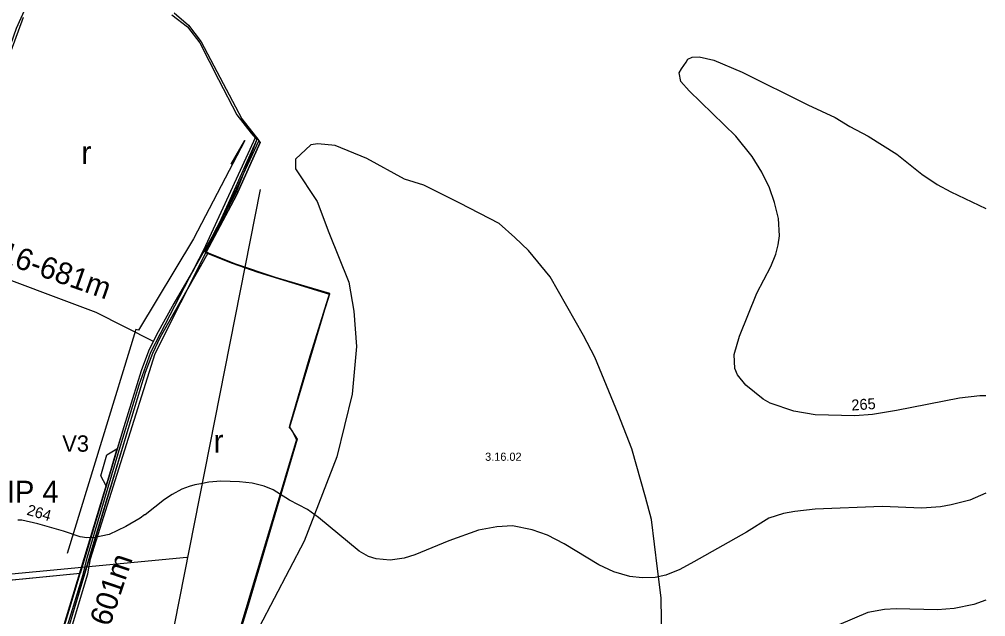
# Model space of a CAD drawing. Extents: x -662500 to -655523, y -1056000 to -1049993.
# Drawn here: x -659686 to -658798, y -1051897 to -1051349 of the extents above; entities that cross this region are included whole.
import ezdxf

# ---------------------------------------------------------------- set-up
doc = ezdxf.new("R2010")
doc.units = 0
for name, color, linetype in [('58', 7, 'Continuous'), ('Vrstva 1', 7, 'Continuous'), ('Vrstva 10', 7, 'Continuous'), ('Vrstva 15', 7, 'Continuous'), ('Vrstva 16', 7, 'Continuous'), ('Vrstva 18', 7, 'Continuous'), ('Vrstva 24', 7, 'Continuous'), ('Vrstva 44', 7, 'Continuous'), ('Vrstva 5', 7, 'Continuous'), ('Vrstva 52', 7, 'Continuous'), ('Vrstva 61', 7, 'Continuous'), ('Vrstva 7', 7, 'Continuous')]:
    doc.layers.add(name, color=color, linetype=linetype)

msp = doc.modelspace()

# ---------------------------------------------------------------- linework, layer by layer
at = {"layer": '58'}
for points in [[(-659819.9, -1051325.04), (-659837.72, -1051368.71), (-659869.54, -1051455.64), (-659887.19, -1051507.97), (-659838.36, -1051532.32), (-659759.05, -1051561.67), (-659712.51, -1051424.5), (-659688.44, -1051356.77), (-659655.81, -1051283.68)], [(-659545.76, -1051344.32), (-659531.38, -1051355.46), (-659520.03, -1051370.23), (-659502.95, -1051403.94), (-659485.94, -1051436.16), (-659472.84, -1051453.09), (-659468.98, -1051457.69), (-659467.67, -1051458.98), (-659486.82, -1051508.01), (-659515.44, -1051562.58), (-659514.06, -1051563.18), (-659490.41, -1051572.48), (-659466.8, -1051580.89), (-659400.85, -1051601.17), (-659419.91, -1051661.07), (-659437.32, -1051721.06), (-659438.03, -1051723.54), (-659435.89, -1051725.64), (-659431.04, -1051734.49), (-659517.29, -1052025.4)]]:
    msp.add_lwpolyline(points, dxfattribs=at)
at = {"layer": 'Vrstva 1'}
for points in [[(-659822.86, -1051335.88), (-659842.66, -1051387.23), (-659885.47, -1051507.41), (-659840.84, -1051529.9), (-659757.26, -1051561.49), (-659712.92, -1051430.24), (-659682.02, -1051346.44)], [(-659543.44, -1051342.71), (-659530.33, -1051353.77), (-659518.69, -1051369.3), (-659481.35, -1051440), (-659464.55, -1051461.63), (-659486.3, -1051510.02), (-659514.2, -1051562.51), (-659488.24, -1051572.77), (-659450.78, -1051585.35), (-659400.7, -1051600.1), (-659437.67, -1051723.3), (-659430.67, -1051734.26), (-659475.46, -1051886.79), (-659522.5, -1052039.32)], [(-659675.39, -1052019.4), (-659679.73, -1052018.94), (-659652.73, -1051933.09), (-659630.06, -1051857.51), (-659807.28, -1051874.94), (-659895.67, -1051883.63), (-659941.66, -1051870.48), (-659948.51, -1051896.4), (-659999.12, -1051901.61), (-659992.31, -1051868.42), (-659984.99, -1051841.61), (-659955.01, -1051741.18), (-660000.31, -1051725.7)]]:
    msp.add_lwpolyline(points, dxfattribs=at)
at = {"layer": 'Vrstva 10'}
msp.add_lwpolyline([(-659676.81, -1052019.63), (-659668.73, -1051995.07), (-659627.27, -1051858.48), (-659623.61, -1051843.33), (-659594.07, -1051744.37), (-659575.69, -1051684.25), (-659565.08, -1051654.18), (-659516.33, -1051560.31), (-659468.47, -1051456.58)], dxfattribs=at)
at = {"layer": 'Vrstva 15'}
msp.add_lwpolyline([(-659562.5, -1051644.38), (-659615.17, -1051617.96), (-659839.2, -1051534.06), (-659887.53, -1051509.79), (-659927, -1051486.15), (-659960.24, -1051460.73), (-660029.15, -1051399.28), (-660110.36, -1051274.6)], dxfattribs=at)
at = {"layer": 'Vrstva 24'}
msp.add_lwpolyline([(-659095, -1051942), (-659096, -1051880), (-659099.5, -1051853.5), (-659105, -1051808), (-659110.5, -1051787.5), (-659123, -1051743), (-659135.5, -1051711), (-659157, -1051659), (-659167.5, -1051639), (-659198, -1051585), (-659218, -1051561), (-659230.5, -1051549), (-659245, -1051536), (-659281, -1051517.5), (-659314, -1051501), (-659332, -1051495.5), (-659366.5, -1051476.5), (-659395.5, -1051464.5), (-659411.5, -1051463), (-659418, -1051464), (-659432, -1051477), (-659432, -1051486), (-659412, -1051516), (-659401.5, -1051544.5), (-659383, -1051590), (-659378.5, -1051616.5), (-659376, -1051649), (-659380, -1051693), (-659394, -1051750.5), (-659424, -1051828), (-659465.5, -1051907)], dxfattribs=at)
at = {"layer": 'Vrstva 44'}
for points in [[(-659464.58, -1051504.83), (-659576.16, -1052069.59), (-659916.29, -1052550.1), (-660191.14, -1052457.81)], [(-659532.04, -1051842.96), (-660363.22, -1051921.99), (-660370.34, -1052014.38)]]:
    msp.add_lwpolyline(points, dxfattribs=at)
at = {"layer": 'Vrstva 5'}
for points in [[(-659822.86, -1051335.88), (-659842.66, -1051387.23), (-659885.47, -1051507.41), (-659840.84, -1051529.9), (-659757.26, -1051561.49), (-659712.92, -1051430.24), (-659682.02, -1051346.44)], [(-659543.44, -1051342.71), (-659530.33, -1051353.77), (-659518.69, -1051369.3), (-659481.35, -1051440), (-659465.8, -1051460.02), (-659490.92, -1051513.91), (-659508.9, -1051548.65), (-659525.42, -1051577.97), (-659543.84, -1051609.56), (-659559.83, -1051638.32), (-659567.15, -1051653.49), (-659573.87, -1051671.4), (-659589.74, -1051722.9), (-659630.06, -1051857.51), (-659895.67, -1051883.63)]]:
    msp.add_lwpolyline(points, dxfattribs=at)
for points in [[(-659675.39, -1052019.4), (-659672.05, -1052019.54), (-659673.62, -1052017.44), (-659585.68, -1051724.17), (-659569.85, -1051672.73), (-659563.24, -1051655.27), (-659556.04, -1051640.22), (-659512.47, -1051563.2), (-659514.2, -1051562.51), (-659486.3, -1051510.02), (-659464.55, -1051461.63), (-659465.8, -1051460.02), (-659490.92, -1051513.91), (-659508.9, -1051548.65), (-659525.42, -1051577.97), (-659543.84, -1051609.56), (-659559.83, -1051638.32), (-659567.15, -1051653.49), (-659573.87, -1051671.4), (-659589.74, -1051722.9), (-659679.73, -1052018.94)], [(-659512.47, -1051563.2), (-659488.24, -1051572.77), (-659450.78, -1051585.35), (-659400.7, -1051600.1), (-659419.91, -1051661.07), (-659438.03, -1051723.54), (-659435.89, -1051725.64), (-659431.04, -1051734.49), (-659518.77, -1052027.22), (-659596.46, -1052023.16), (-659672.05, -1052019.54), (-659673.62, -1052017.44), (-659667.62, -1051998.06), (-659648.39, -1051934.34), (-659617.96, -1051831.4), (-659585.68, -1051724.17), (-659569.85, -1051672.73), (-659563.24, -1051655.27), (-659556.04, -1051640.22), (-659522.01, -1051580.5)]]:
    msp.add_lwpolyline(points, close=True, dxfattribs=at)
at = {"layer": 'Vrstva 52'}
msp.add_lwpolyline([(-659491.33, -1051481.73), (-659478.69, -1051460), (-659525.72, -1051550.06), (-659576.28, -1051634.12), (-659578.84, -1051633.58), (-659641.79, -1051839.33)], dxfattribs=at)
at = {"layer": 'Vrstva 61'}
msp.add_lwpolyline([(-659672.38, -1052015.37), (-659642.55, -1051923.07), (-659623.02, -1051857.8), (-659620.46, -1051844.08), (-659560.95, -1051655.65), (-659514.2, -1051562.51), (-659490.46, -1051510.68), (-659467.3, -1051458.53)], dxfattribs=at)
msp.add_lwpolyline([(-659605.93, -1051777.11), (-659611.06, -1051767.83), (-659605.52, -1051748.61), (-659596.17, -1051743.23)], close=True, dxfattribs=at)
at = {"layer": 'Vrstva 7'}
for p, q in [((-659077.44, -1051394.04), (-659073.03, -1051387.91)), ((-659073.03, -1051387.91), (-659071.39, -1051385.08)), ((-659071.39, -1051385.08), (-659067.45, -1051383.22)), ((-659067.45, -1051383.22), (-659060.99, -1051383.04)), ((-659060.99, -1051383.04), (-659047.69, -1051386.06)), ((-659047.69, -1051386.06), (-659021.49, -1051397.03)), ((-659079.35, -1051397.57), (-659077.44, -1051394.04)), ((-659077.87, -1051405.57), (-659079.35, -1051397.57)), ((-659021.49, -1051397.03), (-658961.12, -1051427.21)), ((-659070.18, -1051414.11), (-659077.87, -1051405.57)), ((-659027.33, -1051455.97), (-659070.18, -1051414.11)), ((-658961.12, -1051427.21), (-658936.2, -1051438.6)), ((-658936.2, -1051438.6), (-658922.53, -1051447)), ((-658922.53, -1051447), (-658905.73, -1051455.97)), ((-659012.38, -1051474.62), (-659027.33, -1051455.97)), ((-658905.73, -1051455.97), (-658879.53, -1051472.49)), ((-659003.55, -1051488.86), (-659012.38, -1051474.62)), ((-658879.53, -1051472.49), (-658856.33, -1051490.71)), ((-658996.57, -1051503.38), (-659003.55, -1051488.86)), ((-658856.33, -1051490.71), (-658842.23, -1051500.25)), ((-658991.73, -1051516.77), (-658996.57, -1051503.38)), ((-658842.23, -1051500.25), (-658829.84, -1051507.09)), ((-658829.84, -1051507.09), (-658797.74, -1051522.29)), ((-658988.03, -1051531.58), (-658991.73, -1051516.77)), ((-658987.17, -1051547.52), (-658988.03, -1051531.58)), ((-658988.31, -1051555.78), (-658987.17, -1051547.52)), ((-658990.73, -1051564.32), (-658988.31, -1051555.78)), ((-658995.15, -1051575.57), (-658990.73, -1051564.32)), ((-659008.1, -1051600.06), (-658995.15, -1051575.57)), ((-659023.91, -1051639.5), (-659008.1, -1051600.06)), ((-659028.75, -1051656.59), (-659023.91, -1051639.5)), ((-659028.18, -1051669.4), (-659028.75, -1051656.59)), ((-659025.9, -1051675.09), (-659028.18, -1051669.4)), ((-659018.07, -1051684.49), (-659025.9, -1051675.09)), ((-659002.12, -1051697.45), (-659018.07, -1051684.49)), ((-658995.72, -1051701.01), (-659002.12, -1051697.45)), ((-658821.87, -1051696.59), (-658879.82, -1051707.99)), ((-658803.18, -1051694.34), (-658821.87, -1051696.59)), ((-658797.74, -1051694.32), (-658803.18, -1051694.34)), ((-658973.93, -1051708.41), (-658995.72, -1051701.01)), ((-658954.43, -1051711.83), (-658973.93, -1051708.41)), ((-658879.82, -1051707.99), (-658901.74, -1051711.69)), ((-658917.98, -1051712.83), (-658954.43, -1051711.83)), ((-658901.74, -1051711.69), (-658917.98, -1051712.83)), ((-659529.66, -1051777.75), (-659536.53, -1051780.29)), ((-659524.62, -1051776.05), (-659529.66, -1051777.75)), ((-659518.95, -1051775.17), (-659524.62, -1051776.05)), ((-659511.73, -1051773.77), (-659518.95, -1051775.17)), ((-659500.68, -1051772.78), (-659511.73, -1051773.77)), ((-659483.67, -1051773.49), (-659500.68, -1051772.78)), ((-659471.99, -1051774.78), (-659483.67, -1051773.49)), ((-659461, -1051777.46), (-659471.99, -1051774.78)), ((-659452.49, -1051780.86), (-659461, -1051777.46)), ((-659545.46, -1051784.97), (-659552.55, -1051789.79)), ((-659536.53, -1051780.29), (-659545.46, -1051784.97)), ((-659437.46, -1051790.19), (-659452.49, -1051780.86)), ((-658797.74, -1051783.71), (-658812.33, -1051790.14)), ((-659552.55, -1051789.79), (-659570.12, -1051803.82)), ((-659420.91, -1051798.74), (-659437.46, -1051790.19)), ((-658892.92, -1051796.12), (-658954.43, -1051798.68)), ((-658856.47, -1051797.69), (-658892.92, -1051796.12)), ((-658839.38, -1051796.4), (-658856.47, -1051797.69)), ((-658829.42, -1051794.7), (-658839.38, -1051796.4)), ((-658812.33, -1051790.14), (-658829.42, -1051794.7)), ((-659570.97, -1051803.82), (-659574.94, -1051806.94)), ((-659570.12, -1051803.82), (-659570.97, -1051803.82)), ((-659411.06, -1051806.28), (-659420.91, -1051798.74)), ((-659373.59, -1051837.12), (-659411.06, -1051806.28)), ((-658983.47, -1051802.38), (-658997.14, -1051806.94)), ((-658973.22, -1051800.53), (-658983.47, -1051802.38)), ((-658954.43, -1051798.68), (-658973.22, -1051800.53)), ((-659683.49, -1051808.78), (-659687.29, -1051808.56)), ((-659668.75, -1051811.9), (-659683.49, -1051808.78)), ((-659645.23, -1051818.7), (-659668.75, -1051811.9)), ((-659587.97, -1051814.45), (-659603.42, -1051821.67)), ((-659574.94, -1051806.94), (-659587.97, -1051814.45)), ((-659246.88, -1051814.63), (-659263.96, -1051817.76)), ((-659232.64, -1051813.92), (-659246.88, -1051814.63)), ((-659214.7, -1051817.48), (-659232.64, -1051813.92)), ((-658997.14, -1051806.94), (-659017.5, -1051819.61)), ((-659629.92, -1051823.94), (-659645.23, -1051818.7)), ((-659623.97, -1051824.93), (-659629.92, -1051823.94)), ((-659603.42, -1051821.67), (-659616.6, -1051824.51)), ((-659263.96, -1051817.76), (-659291.01, -1051827.58)), ((-659200.32, -1051822.32), (-659214.7, -1051817.48)), ((-659185.08, -1051830.43), (-659200.32, -1051822.32)), ((-659017.5, -1051819.61), (-659066.05, -1051846.95)), ((-659616.6, -1051824.51), (-659623.97, -1051824.93)), ((-659291.01, -1051827.58), (-659322.34, -1051840.54)), ((-659153.19, -1051849.65), (-659185.08, -1051830.43)), ((-659365.05, -1051841.97), (-659373.59, -1051837.12)), ((-659357.93, -1051844.1), (-659365.05, -1051841.97)), ((-659322.34, -1051840.54), (-659332.31, -1051843.67)), ((-659345.12, -1051845.52), (-659357.93, -1051844.1)), ((-659332.31, -1051843.67), (-659345.12, -1051845.52)), ((-659139.52, -1051856.2), (-659153.19, -1051849.65)), ((-659066.05, -1051846.95), (-659078.87, -1051854.07)), ((-659124.71, -1051860.33), (-659139.52, -1051856.2)), ((-659091.68, -1051859.19), (-659101.65, -1051861.19)), ((-659078.87, -1051854.07), (-659091.68, -1051859.19)), ((-659113.32, -1051861.47), (-659124.71, -1051860.33)), ((-659101.65, -1051861.19), (-659113.32, -1051861.47)), ((-658808.63, -1051886.1), (-658826.57, -1051889.66)), ((-658797.74, -1051882.1), (-658808.63, -1051886.1)), ((-658906.02, -1051893.51), (-658932.78, -1051904.76)), ((-658890.64, -1051890.66), (-658906.02, -1051893.51)), ((-658880.1, -1051889.95), (-658890.64, -1051890.66)), ((-658841.95, -1051891.09), (-658880.1, -1051889.95)), ((-658826.57, -1051889.66), (-658841.95, -1051891.09))]:
    msp.add_line(p, q, dxfattribs=at)

# ---------------------------------------------------------------- texts
at = {"layer": 'Vrstva 16'}
msp.add_text('C16-681m', height=20, rotation=340.57276, dxfattribs=at).set_placement((-659723.73, -1051564.56))
at = {"layer": 'Vrstva 18'}
msp.add_text('C11-601m', height=20, rotation=71.3406, dxfattribs=at).set_placement((-659621.34, -1051962.07))
at = {"layer": 'Vrstva 24'}
msp.add_text('3.16.02', height=7.5, dxfattribs=at).set_placement((-659257.77, -1051754.12))
at = {"layer": 'Vrstva 5'}
for p in [(-659628.97, -1051481.44), (-659507.48, -1051746.58)]:
    msp.add_text('r', height=21, dxfattribs=at).set_placement(p)
at = {"layer": 'Vrstva 52'}
msp.add_text('IP 4', height=20, dxfattribs=at).set_placement((-659697.32, -1051792.45))
at = {"layer": 'Vrstva 61'}
msp.add_text('V3', height=15, dxfattribs=at).set_placement((-659646.43, -1051745.75))
at = {"layer": 'Vrstva 7'}
for s, rotation, p in [('265', 4.01411, (-658920.8, -1051708.01)), ('264', 343.8711, (-659679.77, -1051803.5))]:
    msp.add_text(s, height=10, rotation=rotation, dxfattribs=at).set_placement(p)

doc.saveas('drawing.dxf')
